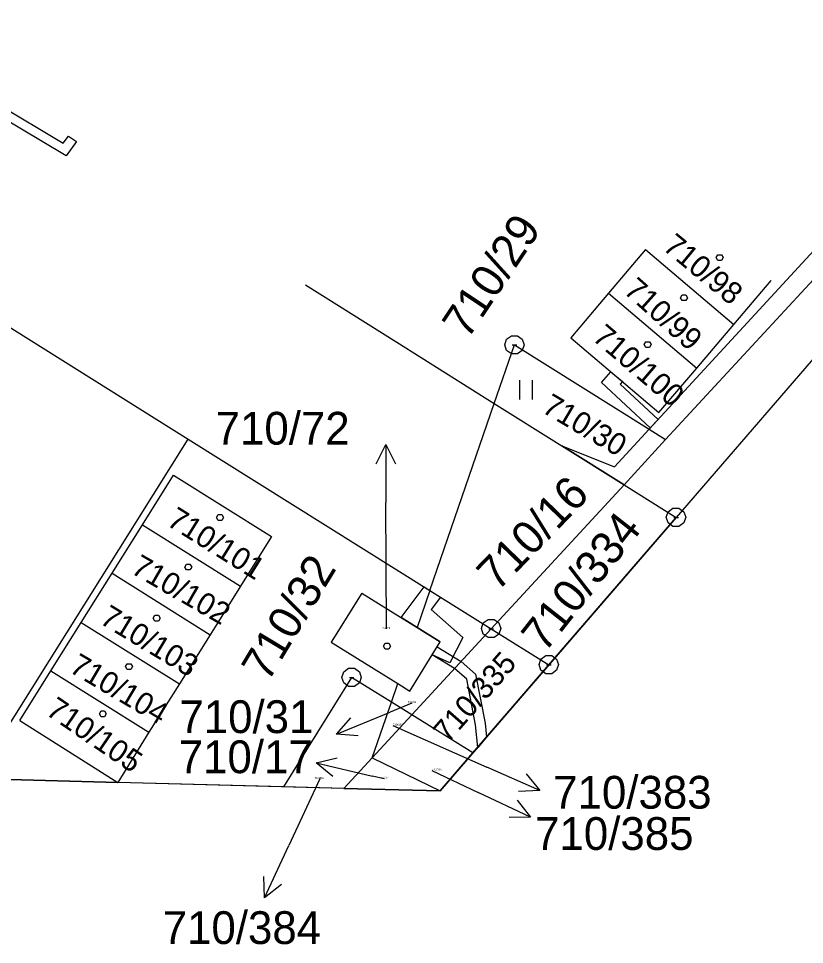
# Model space of a CAD drawing. Extents: x -759699 to -757730, y -1172308 to -1170857.
# Drawn here: x -757843.46 to -757802.68, y -1171045.34 to -1170997.32 of the extents above; entities that cross this region are included whole.
import ezdxf

# ---------------------------------------------------------------- set-up
doc = ezdxf.new("R2010")
doc.units = 0
for name, color, linetype in [('Vrstva 1', 7, 'Continuous'), ('Vrstva 11', 7, 'Continuous'), ('Vrstva 12', 7, 'Continuous'), ('Vrstva 13', 7, 'Continuous'), ('Vrstva 2', 7, 'Continuous'), ('Vrstva 3', 7, 'Continuous'), ('Vrstva 5', 7, 'Continuous'), ('Vrstva 7', 7, 'Continuous'), ('Vrstva 8', 7, 'Continuous')]:
    doc.layers.add(name, color=color, linetype=linetype)

msp = doc.modelspace()

# ---------------------------------------------------------------- linework, layer by layer
at = {"layer": 'Vrstva 1'}
for p, q in [((-757810.92, -1171009.3), (-757812.84, -1171011.57)), ((-757810.92, -1171009.3), (-757810.92, -1171009.3)), ((-757810.92, -1171009.3), (-757806.35, -1171013.19)), ((-757828.57, -1171011.14), (-757828.57, -1171011.14)), ((-757828.57, -1171011.14), (-757828.57, -1171011.14)), ((-757828.57, -1171011.14), (-757823.83, -1171014.11)), ((-757806.35, -1171013.19), (-757804.41, -1171010.9)), ((-757804.41, -1171010.9), (-757804.41, -1171010.9)), ((-757804.41, -1171010.9), (-757804.41, -1171010.9)), ((-757846.94, -1171011.43), (-757834.65, -1171019.13)), ((-757812.84, -1171011.57), (-757814.8, -1171013.88)), ((-757812.84, -1171011.57), (-757808.27, -1171015.45)), ((-757808.27, -1171015.45), (-757806.35, -1171013.19)), ((-757823.83, -1171014.11), (-757823.83, -1171014.11)), ((-757823.83, -1171014.11), (-757818.77, -1171017.28)), ((-757814.8, -1171013.88), (-757810.23, -1171017.76)), ((-757818.77, -1171017.28), (-757817.72, -1171014.25)), ((-757817.72, -1171014.25), (-757810.74, -1171018.62)), ((-757817.72, -1171014.25), (-757817.72, -1171014.25)), ((-757810.23, -1171017.76), (-757808.27, -1171015.45)), ((-757822.11, -1171026.98), (-757818.77, -1171017.28)), ((-757818.77, -1171017.28), (-757812.04, -1171021.5)), ((-757810.74, -1171018.62), (-757809.88, -1171019.16)), ((-757845.69, -1171036.74), (-757834.65, -1171019.13)), ((-757834.65, -1171019.13), (-757822.11, -1171026.98)), ((-757812.04, -1171021.5), (-757809.88, -1171019.16)), ((-757809.88, -1171019.16), (-757809.88, -1171019.16)), ((-757837.03, -1171023.58), (-757835.42, -1171021.01)), ((-757835.42, -1171021.01), (-757830.33, -1171024.19)), ((-757818.93, -1171028.97), (-757812.04, -1171021.5)), ((-757812.04, -1171021.5), (-757809.34, -1171023.2)), ((-757815.94, -1171030.84), (-757809.34, -1171023.2)), ((-757809.34, -1171023.2), (-757809.34, -1171023.2)), ((-757838.6, -1171026.09), (-757837.03, -1171023.58)), ((-757837.03, -1171023.58), (-757831.94, -1171026.76)), ((-757830.33, -1171024.19), (-757831.94, -1171026.76)), ((-757840.2, -1171028.64), (-757838.6, -1171026.09)), ((-757838.6, -1171026.09), (-757833.52, -1171029.28)), ((-757831.94, -1171026.76), (-757833.52, -1171029.28)), ((-757825.64, -1171027.12), (-757827.23, -1171029.66)), ((-757825.64, -1171027.12), (-757822.77, -1171028.9)), ((-757822.11, -1171026.98), (-757822.77, -1171028.9)), ((-757822.11, -1171026.98), (-757818.93, -1171028.97)), ((-757841.77, -1171031.15), (-757840.2, -1171028.64)), ((-757840.2, -1171028.64), (-757835.11, -1171031.82)), ((-757823.05, -1171033.44), (-757818.93, -1171028.97)), ((-757822.77, -1171028.9), (-757821.57, -1171029.64)), ((-757818.93, -1171028.97), (-757815.94, -1171030.84)), ((-757833.52, -1171029.28), (-757835.11, -1171031.82)), ((-757827.23, -1171029.66), (-757823.78, -1171031.81)), ((-757823.15, -1171032.2), (-757821.57, -1171029.64)), ((-757817.23, -1171032.34), (-757815.94, -1171030.84)), ((-757843.38, -1171033.72), (-757841.77, -1171031.15)), ((-757841.77, -1171031.15), (-757836.69, -1171034.34)), ((-757835.11, -1171031.82), (-757836.69, -1171034.34)), ((-757826.17, -1171031.5), (-757829.7, -1171037.17)), ((-757824.11, -1171032.78), (-757826.17, -1171031.5)), ((-757824.11, -1171032.78), (-757823.78, -1171031.81)), ((-757823.78, -1171031.81), (-757823.15, -1171032.2)), ((-757819.88, -1171035.41), (-757817.23, -1171032.34)), ((-757825.11, -1171035.67), (-757824.11, -1171032.78)), ((-757823.05, -1171033.44), (-757824.11, -1171032.78)), ((-757843.38, -1171033.72), (-757838.3, -1171036.94)), ((-757825.11, -1171035.67), (-757823.05, -1171033.44)), ((-757819.88, -1171035.41), (-757823.05, -1171033.44)), ((-757836.69, -1171034.34), (-757838.3, -1171036.94)), ((-757826.57, -1171037.25), (-757825.11, -1171035.67)), ((-757825.11, -1171035.67), (-757821.58, -1171037.38)), ((-757821.58, -1171037.38), (-757819.88, -1171035.41)), ((-757845.69, -1171036.74), (-757838.3, -1171036.94)), ((-757829.7, -1171037.17), (-757838.3, -1171036.94)), ((-757826.57, -1171037.25), (-757829.7, -1171037.17)), ((-757826.57, -1171037.25), (-757821.58, -1171037.38))]:
    msp.add_line(p, q, dxfattribs=at)
at = {"layer": 'Vrstva 11'}
for p, q in [((-757790.05, -1171000.85), (-757821.58, -1171037.38)), ((-757838.3, -1171036.94), (-757845.69, -1171036.74)), ((-757826.57, -1171037.25), (-757838.3, -1171036.94)), ((-757821.58, -1171037.38), (-757826.57, -1171037.25))]:
    msp.add_line(p, q, dxfattribs=at)
at = {"layer": 'Vrstva 12'}
for p, q in [((-757810.92, -1171009.3), (-757812.84, -1171011.57)), ((-757810.92, -1171009.3), (-757806.35, -1171013.19)), ((-757810.92, -1171009.3), (-757810.92, -1171009.3)), ((-757810.92, -1171009.3), (-757806.35, -1171013.19)), ((-757806.35, -1171013.19), (-757804.41, -1171010.9)), ((-757804.41, -1171010.9), (-757804.41, -1171010.9)), ((-757804.41, -1171010.9), (-757804.41, -1171010.9)), ((-757804.41, -1171010.9), (-757804.41, -1171010.9)), ((-757812.84, -1171011.57), (-757814.8, -1171013.88)), ((-757812.84, -1171011.57), (-757808.27, -1171015.45)), ((-757812.84, -1171011.57), (-757808.27, -1171015.45)), ((-757808.27, -1171015.45), (-757806.35, -1171013.19)), ((-757814.8, -1171013.88), (-757810.23, -1171017.76)), ((-757810.23, -1171017.76), (-757808.27, -1171015.45)), ((-757837.03, -1171023.58), (-757835.42, -1171021.01)), ((-757835.42, -1171021.01), (-757830.33, -1171024.19)), ((-757838.6, -1171026.09), (-757837.03, -1171023.58)), ((-757837.03, -1171023.58), (-757831.94, -1171026.76)), ((-757837.03, -1171023.58), (-757831.94, -1171026.76)), ((-757830.33, -1171024.19), (-757831.94, -1171026.76)), ((-757840.2, -1171028.64), (-757838.6, -1171026.09)), ((-757838.6, -1171026.09), (-757833.52, -1171029.28)), ((-757838.6, -1171026.09), (-757833.52, -1171029.28)), ((-757831.94, -1171026.76), (-757833.52, -1171029.28)), ((-757825.64, -1171027.12), (-757827.23, -1171029.66)), ((-757825.64, -1171027.12), (-757822.77, -1171028.9)), ((-757841.77, -1171031.15), (-757840.2, -1171028.64)), ((-757840.2, -1171028.64), (-757835.11, -1171031.82)), ((-757840.2, -1171028.64), (-757835.11, -1171031.82)), ((-757822.77, -1171028.9), (-757821.57, -1171029.64)), ((-757833.52, -1171029.28), (-757835.11, -1171031.82)), ((-757827.23, -1171029.66), (-757823.78, -1171031.81)), ((-757823.15, -1171032.2), (-757821.57, -1171029.64)), ((-757843.38, -1171033.72), (-757841.77, -1171031.15)), ((-757841.77, -1171031.15), (-757836.69, -1171034.34)), ((-757841.77, -1171031.15), (-757836.69, -1171034.34)), ((-757835.11, -1171031.82), (-757836.69, -1171034.34)), ((-757823.78, -1171031.81), (-757823.15, -1171032.2)), ((-757843.38, -1171033.72), (-757838.3, -1171036.94)), ((-757836.69, -1171034.34), (-757838.3, -1171036.94))]:
    msp.add_line(p, q, dxfattribs=at)
at = {"layer": 'Vrstva 13'}
for p, q in [((-757851.94, -1170997.32), (-757841.13, -1171003.79)), ((-757840.99, -1171004.45), (-757852.41, -1170997.62)), ((-757841.13, -1171003.79), (-757840.87, -1171003.43)), ((-757840.87, -1171003.43), (-757840.44, -1171003.7)), ((-757840.44, -1171003.7), (-757840.99, -1171004.45)), ((-757810.74, -1171018.62), (-757799.59, -1171006.53)), ((-757798.84, -1171007.19), (-757809.88, -1171019.16)), ((-757813.2, -1171016.19), (-757812.73, -1171015.64)), ((-757812.73, -1171015.64), (-757812.12, -1171016.15)), ((-757810.68, -1171018.55), (-757813.2, -1171016.19)), ((-757812.12, -1171016.15), (-757812.24, -1171016.29)), ((-757812.24, -1171016.29), (-757810.27, -1171018.11)), ((-757810.27, -1171018.11), (-757810.68, -1171018.55)), ((-757812.54, -1171020.57), (-757810.74, -1171018.62)), ((-757809.88, -1171019.16), (-757812.04, -1171021.5)), ((-757812.04, -1171021.5), (-757815.26, -1171019.48)), ((-757815.26, -1171019.48), (-757812.54, -1171020.57)), ((-757823.61, -1171028.38), (-757822.41, -1171026.79)), ((-757822.41, -1171026.79), (-757822.11, -1171026.98)), ((-757822.11, -1171026.98), (-757821.56, -1171027.33)), ((-757821.56, -1171027.33), (-757822.04, -1171027.97)), ((-757822.04, -1171027.97), (-757820.41, -1171029.43)), ((-757822.77, -1171028.9), (-757823.61, -1171028.38)), ((-757821.57, -1171029.64), (-757822.77, -1171028.9)), ((-757820.41, -1171029.43), (-757821.07, -1171030.74)), ((-757822, -1171030.33), (-757821.57, -1171029.64)), ((-757822, -1171030.33), (-757821.73, -1171029.9)), ((-757821.73, -1171029.9), (-757820.49, -1171030.66)), ((-757821.07, -1171030.74), (-757822, -1171030.33)), ((-757820.83, -1171031.03), (-757822, -1171030.33)), ((-757820.49, -1171030.66), (-757819.74, -1171031.32)), ((-757820.2, -1171031.58), (-757820.83, -1171031.03)), ((-757819.74, -1171031.32), (-757819.24, -1171033.87)), ((-757819.74, -1171033.95), (-757820.2, -1171031.58)), ((-757819.63, -1171035.12), (-757819.74, -1171033.95)), ((-757819.24, -1171033.87), (-757819.18, -1171034.59)), ((-757819.18, -1171034.59), (-757819.63, -1171035.12))]:
    msp.add_line(p, q, dxfattribs=at)
at = {"layer": 'Vrstva 3'}
for p, q in [((-757817.465, -1171016.075), (-757817.465, -1171017.08)), ((-757816.795, -1171017.08), (-757816.795, -1171016.075))]:
    msp.add_line(p, q, dxfattribs=at)
at = {"layer": 'Vrstva 5'}
for points in [[(-757806.99, -1171009.57), (-757806.9, -1171009.72), (-757806.99, -1171009.87), (-757807.17, -1171009.87), (-757807.26, -1171009.72), (-757807.17, -1171009.57)], [(-757808.84, -1171011.65), (-757808.75, -1171011.8), (-757808.84, -1171011.95), (-757809.02, -1171011.95), (-757809.11, -1171011.8), (-757809.02, -1171011.65)], [(-757810.72, -1171014.08), (-757810.63, -1171014.23), (-757810.72, -1171014.38), (-757810.9, -1171014.38), (-757810.99, -1171014.23), (-757810.9, -1171014.08)], [(-757832.91, -1171023.05), (-757832.82, -1171023.2), (-757832.91, -1171023.35), (-757833.09, -1171023.35), (-757833.18, -1171023.2), (-757833.09, -1171023.05)], [(-757834.56, -1171025.62), (-757834.47, -1171025.77), (-757834.56, -1171025.92), (-757834.74, -1171025.92), (-757834.83, -1171025.77), (-757834.74, -1171025.62)], [(-757836.2, -1171028.27), (-757836.11, -1171028.42), (-757836.2, -1171028.57), (-757836.38, -1171028.57), (-757836.47, -1171028.42), (-757836.38, -1171028.27)], [(-757824.25, -1171029.72), (-757824.16, -1171029.87), (-757824.25, -1171030.02), (-757824.43, -1171030.02), (-757824.52, -1171029.87), (-757824.43, -1171029.72)], [(-757837.63, -1171030.78), (-757837.54, -1171030.93), (-757837.63, -1171031.08), (-757837.81, -1171031.08), (-757837.9, -1171030.93), (-757837.81, -1171030.78)], [(-757838.99, -1171033.23), (-757838.9, -1171033.38), (-757838.99, -1171033.53), (-757839.17, -1171033.53), (-757839.26, -1171033.38), (-757839.17, -1171033.23)]]:
    msp.add_lwpolyline(points, close=True, dxfattribs=at)
at = {"layer": 'Vrstva 7'}
for p, q in [((-757824.399, -1171019.42), (-757824.39, -1171022.42)), ((-757824.37, -1171028.98), (-757824.39, -1171022.42)), ((-757823.05, -1171032.82), (-757824.18, -1171033.29)), ((-757826.951, -1171034.439), (-757824.18, -1171033.29)), ((-757824.04, -1171033.99), (-757819.15, -1171036.14)), ((-757828.009, -1171035.918), (-757825.09, -1171036.61)), ((-757816.405, -1171037.351), (-757819.15, -1171036.14)), ((-757824.48, -1171036.75), (-757825.09, -1171036.61)), ((-757822.01, -1171036.32), (-757819.6, -1171037.46)), ((-757827.83, -1171036.76), (-757829.43, -1171040.21)), ((-757816.888, -1171038.742), (-757819.6, -1171037.46)), ((-757830.693, -1171042.931), (-757829.43, -1171040.21))]:
    msp.add_line(p, q, dxfattribs=at)
for points in [[(-757824.896, -1171020.422), (-757824.399, -1171019.42), (-757823.896, -1171020.419)], [(-757825.836, -1171034.518), (-757826.951, -1171034.439), (-757826.219, -1171033.594)], [(-757827.151, -1171036.635), (-757828.009, -1171035.918), (-757826.921, -1171035.662)], [(-757817.118, -1171036.49), (-757816.405, -1171037.351), (-757817.522, -1171037.405)], [(-757817.578, -1171037.862), (-757816.888, -1171038.742), (-757818.005, -1171038.766)], [(-757829.819, -1171042.235), (-757830.693, -1171042.931), (-757830.726, -1171041.814)]]:
    msp.add_lwpolyline(points, dxfattribs=at)
at = {"layer": 'Vrstva 8'}
for p, q in [((-757817.84, -1171014.25), (-757817.6, -1171014.25)), ((-757809.46, -1171023.2), (-757809.22, -1171023.2)), ((-757819.05, -1171028.97), (-757818.81, -1171028.97)), ((-757816.06, -1171030.84), (-757815.82, -1171030.84)), ((-757826.29, -1171031.5), (-757826.05, -1171031.5))]:
    msp.add_line(p, q, dxfattribs=at)
for points in [[(-757817.57, -1171013.77), (-757817.32, -1171013.95), (-757817.22, -1171014.24), (-757817.32, -1171014.53), (-757817.57, -1171014.71), (-757817.88, -1171014.71), (-757818.13, -1171014.53), (-757818.23, -1171014.24), (-757818.13, -1171013.95), (-757817.88, -1171013.77)], [(-757809.19, -1171022.72), (-757808.94, -1171022.9), (-757808.84, -1171023.19), (-757808.94, -1171023.48), (-757809.19, -1171023.66), (-757809.5, -1171023.66), (-757809.75, -1171023.48), (-757809.85, -1171023.19), (-757809.75, -1171022.9), (-757809.5, -1171022.72)], [(-757818.78, -1171028.49), (-757818.53, -1171028.67), (-757818.43, -1171028.96), (-757818.53, -1171029.25), (-757818.78, -1171029.43), (-757819.09, -1171029.43), (-757819.34, -1171029.25), (-757819.44, -1171028.96), (-757819.34, -1171028.67), (-757819.09, -1171028.49)], [(-757815.79, -1171030.36), (-757815.54, -1171030.54), (-757815.44, -1171030.83), (-757815.54, -1171031.12), (-757815.79, -1171031.3), (-757816.1, -1171031.3), (-757816.35, -1171031.12), (-757816.45, -1171030.83), (-757816.35, -1171030.54), (-757816.1, -1171030.36)], [(-757826.02, -1171031.02), (-757825.77, -1171031.2), (-757825.67, -1171031.49), (-757825.77, -1171031.78), (-757826.02, -1171031.96), (-757826.33, -1171031.96), (-757826.58, -1171031.78), (-757826.68, -1171031.49), (-757826.58, -1171031.2), (-757826.33, -1171031.02)]]:
    msp.add_lwpolyline(points, close=True, dxfattribs=at)

# ---------------------------------------------------------------- texts
at = {"layer": 'Vrstva 2'}
for s, height, rotation, p in [('710/29', 1.7, 56.2072, (-757820.158, -1171014.013)), ('710/98', 1.14, 320.4553, (-757810.085, -1171009.266)), ('710/99', 1.14, 318.2781, (-757812.112, -1171011.512)), ('710/100', 1.14, 319.5386, (-757813.739, -1171013.953)), ('710/30', 1.14, 329.4507, (-757816.363, -1171017.701)), ('710/16', 1.7, 45.8939, (-757818.605, -1171027.08)), ('710/101', 1.14, 328.0756, (-757835.825, -1171023.564)), ('710/334', 1.7, 51.7954, (-757816.15, -1171030.264)), ('710/102', 1.14, 329.9664, (-757837.682, -1171026.05)), ('710/32', 1.7, 58.9001, (-757830.516, -1171031.788)), ('710/103', 1.14, 328.8205, (-757839.304, -1171028.652)), ('710/104', 1.14, 329.3934, (-757840.883, -1171031.171)), ('710/335', 1.14, 48.816, (-757821.183, -1171034.948)), ('710/105', 1.14, 325.6692, (-757842.099, -1171033.38))]:
    msp.add_text(s, height=height, rotation=rotation, dxfattribs=at).set_placement(p)
for s, p in [('710/72', (-757824.593, -1171028.98)), ('710/31', (-757823.256, -1171032.82)), ('710/383', (-757824.026, -1171033.99)), ('710/385', (-757821.996, -1171036.32)), ('710/384', (-757828.098, -1171036.76)), ('710/17', (-757824.678, -1171036.75))]:
    msp.add_text(s, height=0.1, dxfattribs=at).set_placement(p)
at = {"layer": 'Vrstva 7'}
for s, p in [('710/72', (-757833.227, -1171019.42)), ('710/31', (-757835.108, -1171034.38)), ('710/17', (-757835.143, -1171036.46)), ('710/383', (-757815.713, -1171038.3)), ('710/385', (-757816.653, -1171040.44)), ('710/384', (-757835.974, -1171045.32))]:
    msp.add_text(s, height=1.7, dxfattribs=at).set_placement(p)

doc.saveas('drawing.dxf')
